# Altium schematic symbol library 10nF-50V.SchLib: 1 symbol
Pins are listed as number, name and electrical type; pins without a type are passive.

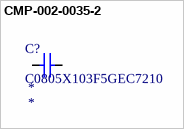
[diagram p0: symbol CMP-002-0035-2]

## CMP-002-0035-2
designator C?, comment C0805X103F5GEC7210
CAP CER 0805 10NF 50V C0G 1%; Value: KEMET; Value: 03014254; Value: SMD; Value: * / *
footprint Capacitor 0805
pins: 1, 2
